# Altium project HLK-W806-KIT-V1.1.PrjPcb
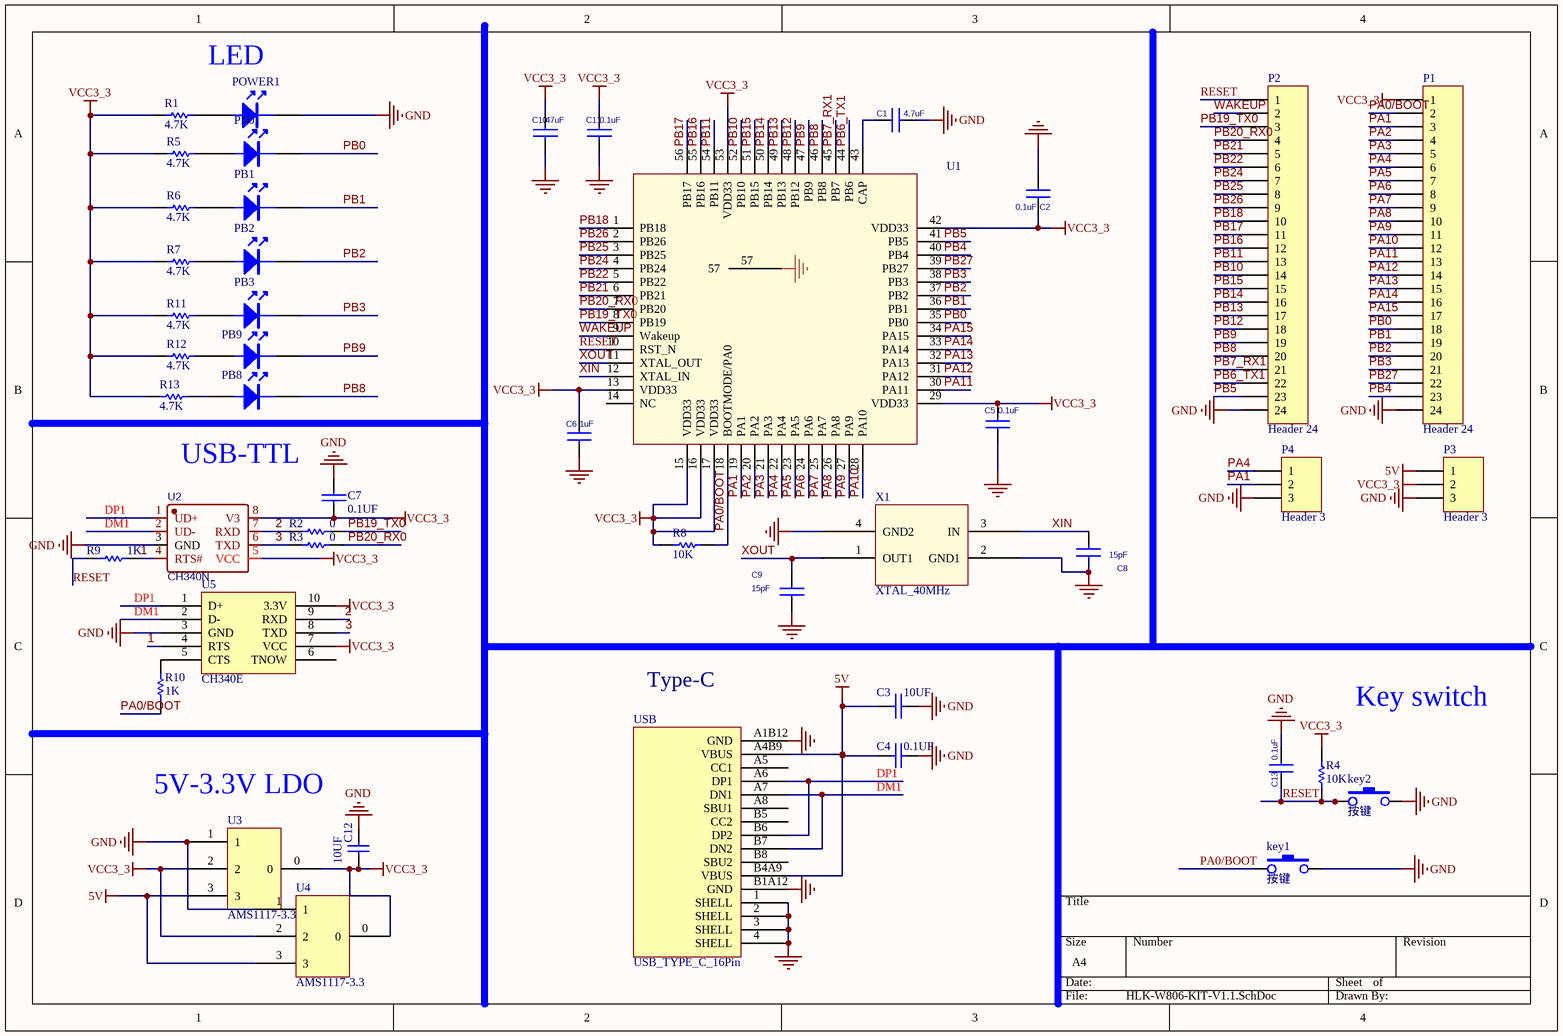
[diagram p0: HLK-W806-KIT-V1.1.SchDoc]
1 sheet, 46 parts. Net scope: global (net labels, ports and power ports of the same name join across sheets).
Board file: HLK-W806-KIT-V1.1.PcbDoc

## Sheet HLK-W806-KIT-V1.1.SchDoc
size A4

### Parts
C1  4.7uF  [0603]
C2  0.1uF  [0603]
C3  10UF  [0603_1]
C4  0.1UF  [0603_1]
C5  0.1uF  [0603]
C6  1uF  [0603]
C7  0.1UF  [0603_1]
C8  15pF  [0603]
C9  15pF  [0603]
C10  47uF  [R0805]
C11  0.1uF  [0603]
C12  10UF  [0603_1]
C13  0.1uF  [0603]
key1  按键  [正按小龟]
key2  按键  [正按小龟]
P1  Header 24  [HDR1X24]
P2  Header 24  [HDR1X24]
P3  Header 3  [HDR1X3]
P4  Header 3  [HDR1X3]
PB0  (no value)  [0603LED]
PB1  (no value)  [0603LED]
PB2  (no value)  [0603LED]
PB3  (no value)  [0603LED]
PB8  (no value)  [0603LED]
PB9  (no value)  [0603LED]
POWER1  (no value)  [0603LED]
R1  4.7K  [0603_1]
R2  0  [0603_1]
R3  0  [0603_1]
R4  10K  [0603_1]
R5  4.7K  [0603_1]
R6  4.7K  [0603_1]
R7  4.7K  [0603_1]
R8  10K  [0603_1]
R9  1K  [0603_1]
R10  1K  [R 0603_L]
R11  4.7K  [0603_1]
R12  4.7K  [0603_1]
R13  4.7K  [0603_1]
U1  Component_1  [LCC56 - duplicate1]  (value not drawn)
U2  CH340N  [SOP8]
U3  AMS1117-3.3  [AMS1117]
U4  AMS1117-3.3  [SOT223]
U5  CH340E  [MSOP10_L]
USB  USB_TYPE_C_16Pin  [USB-C-16PIN-1]
X1  XTAL_40MHz  [SMD-3225]

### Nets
5V: C3.2 C4.2 P3.1 U3.3 U4.3 USB.A4B9(VBUS) USB.B4A9(VBUS)
GND: C1.2 C2.1 C3.1 C4.1 C5.1 C6.2 C7.1 C8.1 C9.2 C10.2 C11.2 C12.1 C13.2 key1.2 key2.2 P1.24 P2.24 P3.3 P4.3 POWER1.2 U1.57 U2.3(GND) U3.1 U4.1 U5.3(GND) USB.1(SHELL) USB.2(SHELL) USB.3(SHELL) USB.4(SHELL) USB.A1B12(GND) USB.B1A12(GND) X1.2(GND1) X1.4(GND2)
VCC3_3: C2.2 C5.2 C6.1 C7.2 C10.1 C11.1 C12.2 P1.1 P3.2 R1.1 R4.2 R5.1 R6.1 R7.1 R8.1 R11.1 R12.1 R13.1 U1.13(VDD33) U1.15(VDD33) U1.16(VDD33) U1.17(VDD33) U1.29(VDD33) U1.42(VDD33) U1.53(VDD33) U2.5(VCC) U2.8(V3) U3.0 U3.2 U4.0 U4.2 U5.7(VCC) U5.10(3.3V)
1: R9.2 U2.4(RTS#) U5.4(RTS)
2: R2.1 U2.7(RXD) U5.9(RXD)
3: R3.1 U2.6(TXD) U5.8(TXD)
DM1: U2.2(UD-) U5.2(D-) USB.A7(DN1) USB.B7(DN2)
DP1: U2.1(UD+) U5.1(D+) USB.A6(DP1) USB.B6(DP2)
PA0/BOOT: key1.1 P1.2 R8.2 R10.1 U1.18(BOOTMODE/PA0)
PA1: P1.3 P4.2 U1.19(PA1)
PA2: P1.4 U1.20(PA2)
PA3: P1.5 U1.21(PA3)
PA4: P1.6 P4.1 U1.22(PA4)
PA5: P1.7 U1.23(PA5)
PA6: P1.8 U1.24(PA6)
PA7: P1.9 U1.25(PA7)
PA8: P1.10 U1.26(PA8)
PA9: P1.11 U1.27(PA9)
PA10: P1.12 U1.28(PA10)
PA11: P1.13 U1.30(PA11)
PA12: P1.14 U1.31(PA12)
PA13: P1.15 U1.32(PA13)
PA14: P1.16 U1.33(PA14)
PA15: P1.17 U1.34(PA15)
PB0: P1.18 PB0.2 U1.35(PB0)
PB1: P1.19 PB1.2 U1.36(PB1)
PB2: P1.20 PB2.2 U1.37(PB2)
PB3: P1.21 PB3.2 U1.38(PB3)
PB4: P1.23 U1.40(PB4)
PB5: P2.23 U1.41(PB5)
PB6_TX1: P2.22 U1.44(PB6)
PB7_RX1: P2.21 U1.45(PB7)
PB8: P2.20 PB8.2 U1.46(PB8)
PB9: P2.19 PB9.2 U1.47(PB9)
PB10: P2.14 U1.52(PB10)
PB11: P2.13 U1.54(PB11)
PB12: P2.18 U1.48(PB12)
PB13: P2.17 U1.49(PB13)
PB14: P2.16 U1.50(PB14)
PB15: P2.15 U1.51(PB15)
PB16: P2.12 U1.55(PB16)
PB17: P2.11 U1.56(PB17)
PB18: P2.10 U1.1(PB18)
PB19_TX0: P2.3 R2.2 U1.8(PB19)
PB20_RX0: P2.4 R3.2 U1.7(PB20)
PB21: P2.5 U1.6(PB21)
PB22: P2.6 U1.5(PB22)
PB24: P2.7 U1.4(PB24)
PB25: P2.8 U1.3(PB25)
PB26: P2.9 U1.2(PB26)
PB27: P1.22 U1.39(PB27)
RESET: C13.1 key2.1 P2.1 R4.1 R9.1 U1.10(RST_N)
WAKEUP: P2.2 U1.9(Wakeup)
XIN: C8.2 U1.12(XTAL_IN) X1.3(IN)
XOUT: C9.1 U1.11(XTAL_OUT) X1.1(OUT1)
NetC1_1: C1.1 U1.43(CAP)
NetPB0_1: PB0.1 R5.2
NetPB1_1: PB1.1 R6.2
NetPB2_1: PB2.1 R7.2
NetPB3_1: PB3.1 R11.2
NetPB8_1: PB8.1 R13.2
NetPB9_1: PB9.1 R12.2
NetPOWER1_1: POWER1.1 R1.2
NetR10_2: R10.2 U5.5(CTS)

Not connected (* = marked no-connect by the designer): U1 14(NC); U5 6(TNOW); USB A5(CC1) A8(SBU1) B5(CC2) B8(SBU2)

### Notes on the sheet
- LED
- USB-TTL
- Type-C
- Key switch
- 5V-3.3V LDO

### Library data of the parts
C1 C2 C5 C6 C8-C11 C13 = CAP NP_Dup1
C3 C4 C7 = CAP: Capacitor
C12 = Cap: Capacitor; Value: 100pF
P1 P2 = Header 24: Header, 24-Pin
P3 P4 = Header 3: Header, 3-Pin
PB0-PB3 PB8 PB9 POWER1 = LED
R1-R13 = Res1: Resistor
U2 = CH340N: BOM_Manufacturer: WCH(Jiangsu Qin Heng); Contributor: LCSC
U3 U4 = Component_1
